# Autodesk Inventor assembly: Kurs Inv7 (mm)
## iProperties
Shininess: 64.0
Length Units: 11269
Angle Units: 11279
Time Units: 11290
Mass Units: 11283
Length Display Precision: 3
Angle Display Precision: 2
Compacted: True
Part Number: Kurs Inv7 (mm)
Document SubType Name: Assembly
Created: 2003-08
Designer: Administratör
Manufacturer: Standard
Standards Organization: Custom
Density: 0.0
Volumn: 0.0
Area: 0.0
PropertySet Name: Model Information
Control State: 0
Master: False
Checked Out: False
Author: Administratör
